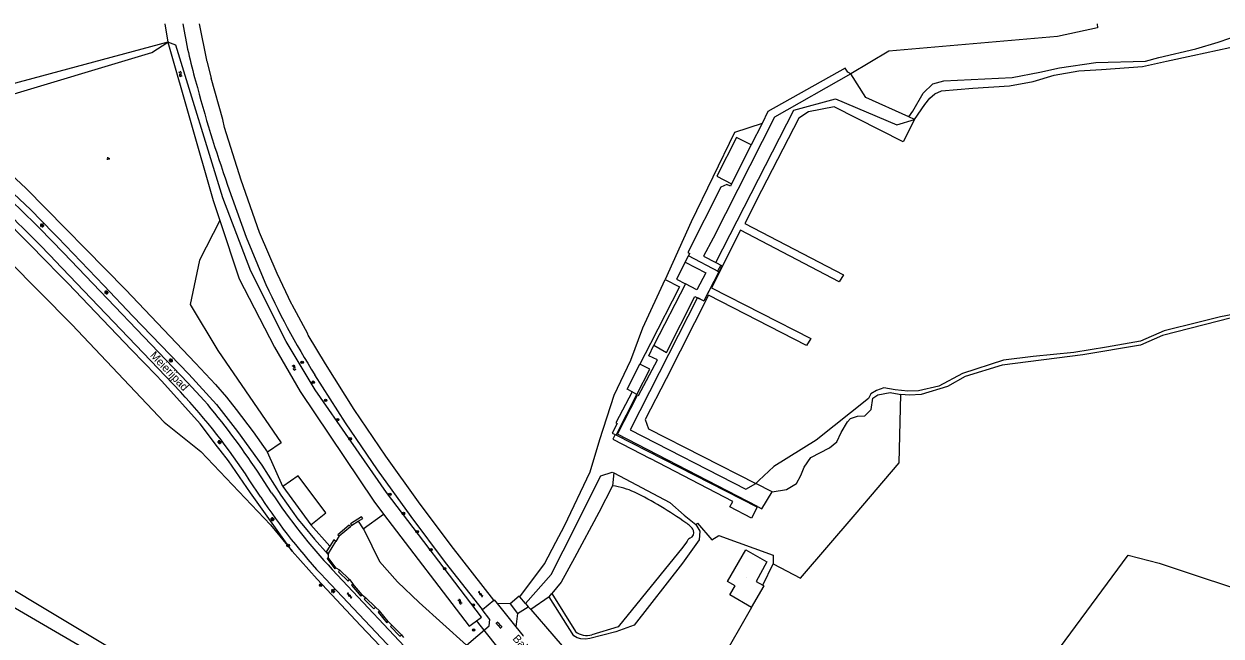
# Model space of a CAD drawing. Extents: x 135990 to 139000, y 393500 to 396000.
# Drawn here: x 137608.5 to 137982.5, y 395808.7 to 396000 of the extents above; entities that cross this region are included whole.
import ezdxf

# ---------------------------------------------------------------- set-up
doc = ezdxf.new("R2010")
doc.units = 0
for name, color, linetype in [('gg-anno-openbare ruimte label', 7, 'Continuous'), ('gg-bbg-luifel en loopbrug', 7, 'Continuous'), ('gg-bbg-overig bouwwerk', 7, 'Continuous'), ('gg-knt-verharding', 7, 'Continuous'), ('gg-kntw-bovenkant insteek waterloop', 7, 'Continuous'), ('gg-kntw-midden sloot', 7, 'Continuous'), ('gg-kwrk-duiker nz buis', 7, 'Continuous'), ('gg-kwrk-kunstwerk niveau 01', 7, 'Continuous'), ('gt-grn-groengrens', 7, 'Continuous'), ('gt-symb-boom', 7, 'Continuous'), ('gt-symb-gesloten verharding', 7, 'Continuous'), ('gt-symb-groenvak', 7, 'Continuous'), ('gt-symb-klinker verharding', 7, 'Continuous'), ('gt-symb-lichtmast', 7, 'Continuous'), ('gt-symb-watersymbool', 7, 'Continuous'), ('gx-grn-maaiveld', 7, 'Continuous'), ('kenmerkpunt-x pandkandidaat', 7, 'Continuous')]:
    doc.layers.add(name, color=color, linetype=linetype)

# ---------------------------------------------------------------- blocks, each defined once
blk = doc.blocks.new('gt0-WA')
at = {"layer": 'gt-symb-watersymbool'}
for centre, start, end in [((-0.32, 0.02), 28.0725, 151.9275), ((0.43, 0.42), 208.0725, 331.9275), ((-0.32, -0.43), 28.0725, 151.9275), ((0.43, -0.03), 208.0725, 331.9275)]:
    blk.add_arc(centre, 0.425, start, end, dxfattribs=at)
blk = doc.blocks.new('gt0-BOOM')
at = {"layer": 'gt-symb-boom'}
for radius in [0.4, 0.2]:
    blk.add_circle((0, 0), radius, dxfattribs=at)
blk = doc.blocks.new('gt0-LMAST')
at = {"layer": 'gt-symb-lichtmast'}
for p, q in [((-0.18, 0.17), (-0.45, 0.44)), ((-0.01, 0.25), (-0.01, 0.62)), ((0.17, 0.17), (0.44, 0.44)), ((-0.26, 0), (-0.63, 0)), ((-0.18, -0.18), (-0.45, -0.45)), ((-0.01, -0.25), (-0.01, -0.63)), ((0.44, -0.45), (0.17, -0.18)), ((0.24, 0), (0.62, 0))]:
    blk.add_line(p, q, dxfattribs=at)
blk.add_circle((-0.01, 0), 0.25, dxfattribs=at)
blk = doc.blocks.new('gt0-GESVH1')
at = {"layer": 'gt-symb-gesloten verharding'}
for p, q in [((-0.99, -0.26), (0.01, 0.24)), ((0.01, -0.26), (-0.99, 0.24)), ((0.01, 0.24), (1.01, -0.26)), ((1.01, 0.24), (0.01, -0.26))]:
    blk.add_line(p, q, dxfattribs=at)
blk = doc.blocks.new('gt0-GRVAK')
at = {"layer": 'gt-symb-groenvak'}
for p, q in [((-0.11, 0.19), (-0.23, 0.24)), ((-0.18, 0.15), (0.09, 0.15)), ((-0.09, 0.21), (-0.16, 0.32)), ((-0.05, 0.21), (-0.05, 0.39)), ((0, 0.21), (0.06, 0.32)), ((0.01, 0.19), (0.13, 0.24)), ((0.26, -0.05), (0.2, 0.06)), ((0.3, -0.05), (0.3, 0.13)), ((0.35, -0.05), (0.41, 0.06)), ((-0.25, -0.23), (-0.36, -0.18)), ((-0.32, -0.26), (-0.05, -0.26)), ((-0.23, -0.21), (-0.29, -0.09)), ((-0.18, -0.2), (-0.18, -0.02)), ((-0.14, -0.21), (-0.07, -0.09)), ((-0.12, -0.23), (0, -0.18)), ((0.24, -0.07), (0.12, -0.02)), ((0.17, -0.11), (0.44, -0.11)), ((0.37, -0.07), (0.49, -0.02))]:
    blk.add_line(p, q, dxfattribs=at)
blk = doc.blocks.new('gt0-KL1')
at = {"layer": 'gt-symb-klinker verharding'}
for p, q in [((-1.15, 0.3), (1.15, 0.3)), ((-1, -0.3), (-1, 0.3)), ((-0.5, 0.3), (-0.5, 0.45)), ((0, -0.3), (0, 0.3)), ((0.5, 0.3), (0.5, 0.45)), ((1, -0.3), (1, 0.3)), ((-1.15, -0.3), (1.15, -0.3)), ((-0.5, -0.45), (-0.5, -0.3)), ((0.5, -0.45), (0.5, -0.3))]:
    blk.add_line(p, q, dxfattribs=at)

msp = doc.modelspace()

# ---------------------------------------------------------------- linework, layer by layer
at = {"layer": 'gg-bbg-luifel en loopbrug'}
for p, q in [((137815.071, 395925.559), (137816.077, 395927.507)), ((137825.585, 395922.504), (137816.077, 395927.507)), ((137825.585, 395922.504), (137820.934, 395913.469)), ((137815.123, 395918.78), (137805.239, 395899.578))]:
    msp.add_line(p, q, dxfattribs=at)
for points in [[(137815.071, 395925.559), (137821.495, 395922.244), (137818.745, 395916.911), (137815.123, 395918.78)], [(137805.239, 395899.578), (137809.17, 395897.327), (137818.12, 395914.854), (137820.934, 395913.469)]]:
    msp.add_lwpolyline(points, dxfattribs=at)
at = {"layer": 'gg-bbg-overig bouwwerk'}
msp.add_line((137799.966, 395884.215), (137798.44, 395885.022), dxfattribs=at)
for points in [[(137798.44, 395885.022), (137793.36, 395875.342), (137793.82, 395875.161), (137792.27, 395872.17), (137793.15, 395871.692), (137792.47, 395870.281), (137804.088, 395864.236)], [(137837.546, 395848.964), (137793.475, 395871.546), (137799.966, 395884.215)], [(137837.546, 395848.964), (137835.827, 395845.609), (137829.045, 395849.084), (137829.921, 395850.794), (137804.088, 395864.236)]]:
    msp.add_lwpolyline(points, dxfattribs=at)
at = {"layer": 'gg-knt-verharding'}
for p, q in [((137631.776, 395911.832), (137618.114, 395926.123)), ((137657.404, 395885.025), (137631.776, 395911.832)), ((137685.845, 395853.527), (137681.429, 395860.213)), ((137682.42, 395852.181), (137678.873, 395857.574)), ((137733.612, 395798.844), (137704.764, 395829.581)), ((137751.706, 395817.057), (137755.299, 395819.996))]:
    msp.add_line(p, q, dxfattribs=at)
for points in [[(137672.098, 395949.59), (137677.856, 395933.349), (137683.16, 395920.513)], [(137664.747, 395882.377), (137659.607, 395887.866), (137620.855, 395928.462)], [(137751.706, 395817.057), (137740.186, 395831.714), (137729.448, 395846.041), (137718.942, 395860.67), (137708.944, 395875.363), (137699.358, 395890.309)], [(137702.666, 395826.565), (137725.342, 395802.51), (137735.141, 395792.166)], [(137746.721, 395805.88), (137753.844, 395811.92), (137754.002, 395813.955), (137751.647, 395817.009), (137751.706, 395817.057)]]:
    msp.add_lwpolyline(points, dxfattribs=at)
for centre, radius, start, end in [((137805.247, 396023.3), 148.95, 188.99975, 196.01765), ((138082.072, 396093.38), 434.458, 194.82725, 199.32733), ((137200.622, 395525.112), 582.483, 43.825601, 49.481054), ((137197.191, 395521.905), 583.582, 43.84019, 49.512308), ((137913.314, 396024.496), 252.554, 204.31336, 212.09476), ((137501.046, 395740.619), 212.84, 33.3325, 42.72432), ((137479.658, 395725.708), 242.494, 33.68838, 40.24639), ((137839.261, 395955.334), 187.722, 213.33253, 223.31072), ((137835.668, 395952.451), 179.535, 213.43565, 223.18672)]:
    msp.add_arc(centre, radius, start, end, dxfattribs=at)
at = {"layer": 'gg-kntw-bovenkant insteek waterloop'}
for points in [[(137749.485, 395813.187), (137751.4, 395814.592), (137721.78, 395853.591), (137699.44, 395885.642), (137690.39, 395900.791), (137679.36, 395922.742), (137670.55, 395945.652), (137655.96, 395993.411), (137653.37, 395994.282)], [(137653.37, 395994.282), (137667.6, 395944.812), (137669.666, 395938.581)], [(137669.666, 395938.581), (137675.7, 395920.381), (137686.72, 395899.041), (137694.71, 395885.171), (137717.75, 395850.852), (137720.813, 395846.838)], [(137565.62, 395846.96), (137681.56, 395777.371), (137724.28, 395751.86), (137777.44, 395720.652)], [(137720.813, 395846.838), (137747.57, 395811.782), (137749.485, 395813.187)]]:
    msp.add_lwpolyline(points, dxfattribs=at)
at = {"layer": 'gg-kntw-midden sloot'}
msp.add_line((137589.061, 395973.293), (137648.402, 395991.059), dxfattribs=at)
at = {"layer": 'gg-kwrk-duiker nz buis'}
msp.add_line((137749.74, 395813.621), (137757.24, 395804.092), dxfattribs=at)
at = {"layer": 'gg-kwrk-kunstwerk niveau 01'}
msp.add_line((137818.88, 395914.48), (137820.934, 395913.469), dxfattribs=at)
for points in [[(137886.758, 395970.109), (137883.135, 395963.186), (137861.583, 395974.059), (137853.623, 395972.536), (137850.588, 395970.537), (137838.925, 395947.982), (137833.715, 395937.597), (137864.533, 395921.632), (137863.177, 395919.399), (137832.36, 395935.588), (137823.298, 395917.498), (137854.342, 395901.755), (137852.985, 395899.523), (137822.39, 395915.263), (137809.139, 395889.133), (137802.571, 395876.403), (137803.563, 395873.486), (137837.117, 395856.373)], [(137824.596, 395925.451), (137848.981, 395973.089), (137861.975, 395976.594), (137881.166, 395968.433), (137886.758, 395970.109)], [(137824.596, 395925.451), (137826.144, 395924.634), (137825.179, 395922.718), (137825.585, 395922.504)], [(137818.88, 395914.48), (137797.862, 395873.168), (137833.994, 395854.621), (137837.117, 395856.373)]]:
    msp.add_lwpolyline(points, dxfattribs=at)
at = {"layer": 'gt-grn-groengrens'}
for p, q in [((137652.508, 396000), (137653.37, 395994.282)), ((137648.402, 395991.059), (137653.37, 395994.282)), ((137689.377, 395855.455), (137684.586, 395866.182)), ((137714.481, 395842.233), (137720.813, 395846.838)), ((137698.134, 395843.476), (137703.98, 395836.8)), ((137706.975, 395840.079), (137710.481, 395842.974)), ((137710.931, 395843.336), (137710.481, 395842.974)), ((137710.931, 395843.336), (137712.898, 395844.59)), ((137712.898, 395844.59), (137714.481, 395842.233)), ((137706.975, 395840.079), (137705.952, 395838.262)), ((137703.571, 395834.536), (137705.952, 395838.262)), ((137703.549, 395834.212), (137703.484, 395833.248)), ((137705.917, 395830.031), (137703.484, 395833.248)), ((137703.571, 395834.536), (137703.549, 395834.212)), ((137705.917, 395830.031), (137707.098, 395829.381)), ((137710.14, 395826.403), (137707.098, 395829.381)), ((137710.14, 395826.403), (137711.19, 395825.026)), ((137714.16, 395821.585), (137711.19, 395825.026)), ((137714.16, 395821.585), (137715.184, 395820.802)), ((137718.269, 395817.749), (137715.184, 395820.802)), ((137718.269, 395817.749), (137719.537, 395816.591)), ((137722.285, 395813.317), (137719.537, 395816.591)), ((137722.285, 395813.317), (137723.45, 395812.119)), ((137726.381, 395809.153), (137723.45, 395812.119)), ((137726.381, 395809.153), (137727.096, 395808.306))]:
    msp.add_line(p, q, dxfattribs=at)
for points in [[(137653.37, 395994.282), (137593.266, 395978.128), (137593.009, 395978.123), (137590.971, 395976.63)], [(137583.881, 395971.44), (137595.258, 395961.396), (137609.091, 395948.656), (137640.202, 395916.987), (137662.095, 395893.96), (137668.288, 395887.358), (137671.792, 395883.404), (137674.77, 395879.565), (137680.086, 395872.536), (137684.586, 395866.182)], [(137580.702, 395969.113), (137591.905, 395959.293), (137599.94, 395951.811), (137610.549, 395941.999), (137617.65, 395934.641), (137619.019, 395933.235), (137619.012, 395933.229), (137633.363, 395918.234), (137642.44, 395908.667), (137660.01, 395890.545), (137668.596, 395881.039), (137675.128, 395872.698), (137682.732, 395862.088), (137688.701, 395852.78), (137690.492, 395850.249), (137694.078, 395845.254), (137695.805, 395843.126), (137699.222, 395839.026), (137703.549, 395834.212)], [(137692.27, 395835.254), (137692.282, 395835.278), (137679.207, 395853.447), (137672.408, 395863.482), (137669.801, 395866.849), (137668.559, 395868.42), (137667.093, 395870.346), (137663.489, 395875.003), (137651.561, 395888.421), (137649.765, 395890.287), (137642.06, 395898.187), (137630.814, 395909.926), (137622.259, 395918.856), (137620.285, 395920.866), (137618.267, 395922.859), (137616.117, 395925.109), (137602.33, 395939.15), (137591.98, 395948.652), (137582.49, 395957.336), (137574.527, 395964.593)], [(137567.447, 395959.407), (137569.101, 395957.805), (137583.607, 395946.156), (137623.456, 395906.066), (137652.312, 395875.597), (137663.763, 395866.434), (137685.519, 395843.526), (137692.27, 395835.254)], [(137669.666, 395938.581), (137663.334, 395926.206), (137660.375, 395912.319), (137669.024, 395897.976), (137688.825, 395869.062), (137684.586, 395866.182)], [(137698.134, 395843.476), (137702.785, 395847.267), (137694.172, 395858.812), (137689.377, 395855.455)], [(137689.377, 395855.455), (137689.379, 395855.452), (137698.134, 395843.476)], [(137710.481, 395842.974), (137710.097, 395843.4), (137706.574, 395840.39), (137706.975, 395840.079)], [(137712.898, 395844.59), (137714.332, 395845.503), (137713.931, 395845.955), (137710.53, 395843.788), (137710.931, 395843.336)], [(137714.481, 395842.233), (137714.781, 395841.785), (137719.498, 395832.053), (137725.17, 395825.684), (137731.917, 395819.185), (137746.721, 395805.88)], [(137703.98, 395836.8), (137702.859, 395835.045), (137703.571, 395834.536)], [(137705.952, 395838.262), (137705.239, 395838.771), (137703.98, 395836.8)], [(137692.27, 395835.254), (137700.12, 395826.542), (137713.615, 395811.996), (137734.076, 395790.503)], [(137703.484, 395833.248), (137703.191, 395833.006), (137705.625, 395829.789), (137705.917, 395830.031)], [(137707.098, 395829.381), (137706.714, 395828.814), (137709.757, 395825.836), (137710.14, 395826.403)], [(137711.19, 395825.026), (137710.754, 395824.654), (137713.723, 395821.213), (137714.16, 395821.585)], [(137715.184, 395820.802), (137714.737, 395820.277), (137717.822, 395817.225), (137718.269, 395817.749)], [(137719.537, 395816.591), (137719.111, 395816.179), (137721.859, 395812.906), (137722.285, 395813.317)], [(137723.45, 395812.119), (137722.974, 395811.711), (137725.905, 395808.745), (137726.381, 395809.153)]]:
    msp.add_lwpolyline(points, dxfattribs=at)
at = {"layer": 'gx-grn-maaiveld'}
for p, q in [((137866.864, 395984.377), (137865.884, 395984.914)), ((137886.758, 395970.109), (137884.914, 395970.942)), ((137839.072, 395968.939), (137835.667, 395962.201)), ((137835.667, 395962.201), (137829.541, 395950.083)), ((137816.077, 395927.507), (137816.486, 395928.308)), ((137813.31, 395917.881), (137804.233, 395900.17)), ((137808.81, 395920.112), (137813.31, 395917.881)), ((137804.233, 395900.17), (137800.921, 395893.709)), ((137792.721, 395859.717), (137792.375, 395855.676)), ((137842.199, 395853.781), (137837.117, 395856.373)), ((137837.546, 395848.964), (137837.657, 395849.181)), ((137818.334, 395843.595), (137818.864, 395843.97)), ((137839.367, 395824.62), (137842.529, 395831.272)), ((137765.211, 395818.861), (137763.345, 395821.011)), ((137772.572, 395820.985), (137766.816, 395816.995)), ((137772.572, 395820.985), (137773.388, 395821.993)), ((137773.388, 395821.993), (137780.751, 395810.129)), ((137760.328, 395818.777), (137756.316, 395818.893)), ((137756.316, 395818.893), (137762.166, 395811.653)), ((137760.328, 395818.777), (137762.664, 395815.813)), ((137762.664, 395815.813), (137766.044, 395817.901)), ((137765.211, 395818.861), (137766.044, 395817.901)), ((137766.816, 395816.995), (137766.044, 395817.901)), ((137766.816, 395816.995), (137788.491, 395791.971)), ((137835.778, 395817.705), (137808.181, 395769.569)), ((137762.664, 395815.813), (137762.166, 395811.653))]:
    msp.add_line(p, q, dxfattribs=at)
for points in [[(137663.185, 396000), (137665.492, 395988.668), (137665.515, 395988.557), (137665.557, 395988.391), (137666.92, 395983.047)], [(137943.83, 396000), (137943.849, 395998.79), (137931.35, 395996.09), (137878.647, 395991.468), (137866.864, 395984.377)], [(137884.914, 395970.942), (137886.214, 395972.72), (137889.374, 395978.399), (137892.407, 395981.286), (137895.875, 395982.272), (137917.216, 395983.268), (137925.827, 395984.895), (137931.978, 395986.312), (137943.381, 395987.923), (137958.911, 395988.393), (137963.05, 395989.487), (137974.571, 395992.214), (137981.62, 395994.297), (137985.202, 395995.505), (137988.668, 395996.156), (137990.79, 395996.032), (137998.375, 395994.09), (138001.004, 395993.111)], [(137886.758, 395970.109), (137889.91, 395974.863), (137891.488, 395976.794), (137893.062, 395978.203), (137895.156, 395979.086), (137904.934, 395979.926), (137916.426, 395980.681), (137923.745, 395982.057), (137930.395, 395983.959), (137938.087, 395985.333), (137945.102, 395985.815), (137957.949, 395986.702), (137965.443, 395988.399), (137973.668, 395990.141), (137985.238, 395992.678)], [(137865.884, 395984.914), (137865.014, 395986.135), (137840.919, 395972.593), (137839.072, 395968.939)], [(137687.53, 395922.006), (137682.068, 395934.871), (137676.364, 395951.156), (137671.097, 395967.651), (137670.596, 395970.192), (137666.92, 395983.047)], [(137866.864, 395984.377), (137842.933, 395970.852), (137823.771, 395933.101), (137820.791, 395927.459), (137824.596, 395925.451)], [(137884.914, 395970.942), (137871.454, 395977.027), (137866.864, 395984.377)], [(137839.072, 395968.939), (137830.505, 395966.13), (137816.929, 395938.155), (137808.81, 395920.112)], [(137835.667, 395962.201), (137831.091, 395964.512), (137824.97, 395952.392), (137829.541, 395950.083)], [(137829.541, 395950.083), (137829.172, 395949.352), (137828.033, 395949.868), (137826.175, 395948.994), (137815.865, 395928.625), (137816.486, 395928.308)], [(137815.071, 395925.559), (137812.32, 395920.227), (137815.123, 395918.78)], [(137824.596, 395925.451), (137826.567, 395924.411), (137820.934, 395913.469)], [(137702.627, 395893.771), (137697.299, 395902.787), (137697.194, 395902.965), (137697.113, 395903.117), (137692.234, 395912.241), (137692.159, 395912.382), (137692.075, 395912.556), (137687.53, 395922.006)], [(137763.345, 395821.011), (137771.13, 395831.34), (137774.693, 395838.107), (137777.35, 395843.152), (137785.36, 395860.061), (137788.35, 395870.2), (137792.85, 395884.041), (137798.07, 395894.89), (137801.86, 395905.051), (137808.81, 395920.112)], [(137986.145, 395909.192), (137982.336, 395908.468), (137975.613, 395906.865), (137964.706, 395904.092), (137957.302, 395900.851), (137946.698, 395898.972), (137936.469, 395897.314), (137923.78, 395896.118), (137914.523, 395894.902), (137901.668, 395890.797), (137894.335, 395886.81), (137887.955, 395885.377), (137884.617, 395885.25), (137880.677, 395885.694), (137877.1, 395886.311), (137874.857, 395885.503), (137873.06, 395884.395), (137872.306, 395882.981), (137855.97, 395869.944), (137842.794, 395861.739), (137838.069, 395857.364), (137837.117, 395856.373)], [(137985.712, 395908.15), (137964.234, 395902.686), (137957.291, 395899.598), (137939.289, 395896.572), (137914.137, 395893.363), (137902.5, 395889.855), (137897.009, 395886.758), (137888.841, 395884.235), (137885.153, 395884.033), (137882.443, 395884.236)], [(137837.657, 395849.181), (137793.868, 395871.768), (137800.165, 395883.975), (137800.45, 395883.859), (137806.448, 395895.023), (137803.718, 395896.283), (137805.239, 395899.578)], [(137755.299, 395819.996), (137741.96, 395837.059), (137731.767, 395850.676), (137721.514, 395864.894), (137711.668, 395879.532), (137702.627, 395893.771)], [(137798.44, 395885.022), (137796.89, 395885.842), (137800.921, 395893.709)], [(137799.966, 395884.215), (137804.018, 395892.122), (137800.921, 395893.709)], [(137842.199, 395853.781), (137846.671, 395854.538), (137849.81, 395856.419), (137851.164, 395858.869), (137852.185, 395861.544), (137854.324, 395864.548), (137860.15, 395867.531), (137862.394, 395869.417), (137863.751, 395872.313), (137865.781, 395875.653), (137866.681, 395876.765), (137868.919, 395877.423), (137871.153, 395877.522), (137873.175, 395879.521), (137873.642, 395883.093), (137875.212, 395884.089), (137879.126, 395884.849), (137881.915, 395884.275), (137882.443, 395884.236)], [(137842.529, 395831.272), (137851.043, 395826.78), (137868.126, 395846.703), (137881.883, 395862.82), (137882.443, 395884.236)], [(137765.211, 395818.861), (137773.21, 395827.981), (137776.93, 395835.377), (137788.695, 395858.763), (137792.209, 395859.986), (137792.721, 395859.717)], [(137792.721, 395859.717), (137810.25, 395850.488), (137814.764, 395846.503), (137818.334, 395843.595)], [(137792.375, 395855.676), (137788.064, 395847.319), (137780.484, 395833.15), (137776.271, 395825.555), (137773.388, 395821.993)], [(137837.657, 395849.181), (137839.051, 395848.462), (137842.199, 395853.781)], [(137818.334, 395843.595), (137819.647, 395841.554), (137819.431, 395838.8), (137814.232, 395831.512), (137799.095, 395812.181), (137793.42, 395810.081), (137785.262, 395807.958), (137783.876, 395807.809), (137782.491, 395807.878), (137781.35, 395808.152), (137780.285, 395808.824), (137772.572, 395820.985)], [(137818.864, 395843.97), (137823.41, 395838.772), (137825.56, 395840.181)], [(137629.084, 395803.757), (137595.011, 395823.592), (137564.274, 395842.137), (137563.356, 395842.713)], [(137825.56, 395840.181), (137842.529, 395834.004), (137842.529, 395831.272)], [(137815.445, 395838.047), (137814.364, 395836.539), (137794.164, 395811.59), (137785.921, 395809.152)], [(137835.778, 395817.705), (137829.05, 395821.624), (137830.656, 395824.381), (137828.315, 395825.736), (137834.056, 395835.66), (137840.545, 395831.927), (137837.239, 395825.82), (137839.367, 395824.62)], [(137863.948, 395713.905), (137899.301, 395760.371), (137924.12, 395794.267), (137953.519, 395833.994), (137963.18, 395831.495), (137977.172, 395826.873), (137998.854, 395819.751), (138022.52, 395810.882), (138049.564, 395801.347)], [(137835.778, 395817.705), (137839.697, 395824.434), (137839.367, 395824.62)], [(137763.345, 395821.011), (137763.213, 395821.163), (137760.328, 395818.777)], [(137755.299, 395819.996), (137755.375, 395820.058), (137756.316, 395818.893)], [(137762.166, 395811.653), (137764.465, 395808.808), (137764.359, 395808.722)]]:
    msp.add_lwpolyline(points, dxfattribs=at)
for centre, radius, start, end in [((137789.456, 395832.881), 22.981, 64.8702, 82.70205), ((137746.776, 395747.7), 118.25, 54.59436, 63.67547), ((137812.279, 395838.541), 6.305, 30.63972, 61.50937), ((137818.455, 395836.606), 3.338, 124.87511, 154.4189), ((137815.902, 395841.135), 1.904, 289.78987, 18.95904), ((137784.286, 395814.668), 5.753, 232.08751, 286.50996)]:
    msp.add_arc(centre, radius, start, end, dxfattribs=at)

# ---------------------------------------------------------------- block references
at = {"layer": 'gt-symb-boom'}
for p in [(137695.368, 395894.253), (137698.819, 395888.031), (137702.709, 395882.383), (137706.469, 395876.337), (137710.38, 395870.369), (137722.788, 395853.034), (137727.021, 395847.025), (137731.341, 395841.367), (137691.011, 395837.025), (137735.597, 395835.732), (137739.9, 395829.783), (137701.178, 395824.617), (137748.867, 395818.427), (137748.956, 395810.624)]:
    msp.add_blockref('gt0-BOOM', p, dxfattribs=at)
at = {"layer": 'gt-symb-gesloten verharding'}
for p, rotation in [((137710.166, 395821.375), 130.01095771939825), ((137751.149, 395821.826), -52.27073010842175)]:
    msp.add_blockref('gt0-GESVH1', p, dxfattribs=dict(at, rotation=rotation))
at = {"layer": 'gt-symb-groenvak'}
msp.add_blockref('gt0-GRVAK', (137634.749, 395957.981), dxfattribs=at)
at = {"layer": 'gt-symb-klinker verharding', "rotation": -47.838118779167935}
msp.add_blockref('gt0-KL1', (137756.897, 395812.164), dxfattribs=at)
at = {"layer": 'gt-symb-lichtmast'}
for p in [(137614.12, 395937.049), (137634.223, 395916.083), (137654.394, 395894.881), (137669.6, 395869.311), (137686.141, 395845.216), (137705.033, 395822.793)]:
    msp.add_blockref('gt0-LMAST', p, dxfattribs=at)
at = {"layer": 'gt-symb-watersymbool'}
for p, rotation in [((137657.364, 395984.298), 112.02484593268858), ((137692.841, 395892.641), -59.15409543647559), ((137744.702, 395819.418), 133.01389340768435)]:
    msp.add_blockref('gt0-WA', p, dxfattribs=dict(at, rotation=rotation))

# ---------------------------------------------------------------- texts
at = {"layer": 'gg-anno-openbare ruimte label'}
for s, rotation, p in [('Meierijpad', 313.7, (137647.67, 395896.25)), ('Baksevenweg', 311.9, (137760.963, 395807.782))]:
    msp.add_text(s, height=2.5, rotation=rotation, dxfattribs=at).set_placement(p)
at = {"layer": 'kenmerkpunt-x pandkandidaat'}
for p in [(137800.079, 395888.871), (137834.059, 395826.868)]:
    msp.add_text('PNDK', height=0.2, dxfattribs=at).set_placement(p)

doc.saveas('drawing.dxf')
